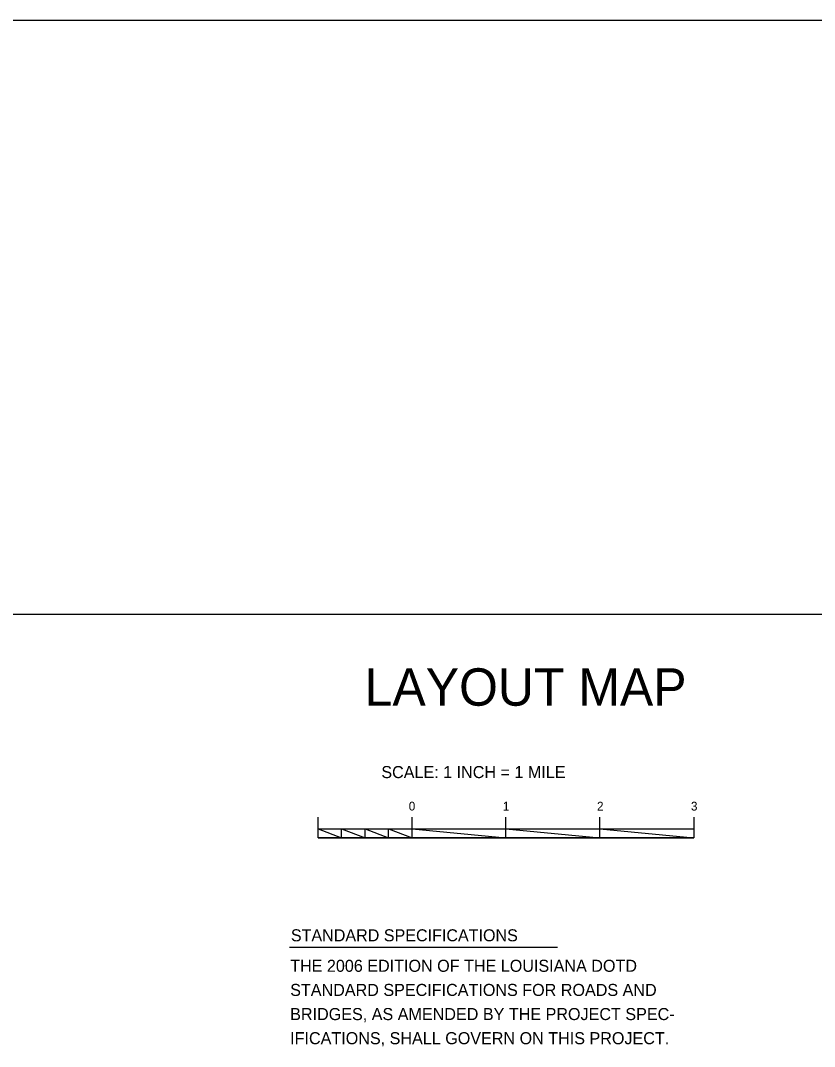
# Model space of a CAD drawing. Extents: x 0.19 to 2.82, y 0.04 to 1.79.
# Drawn here: x 1.074 to 1.779, y 0.111 to 1.021 of the extents above; entities that cross this region are included whole.
import ezdxf

# ---------------------------------------------------------------- set-up
doc = ezdxf.new("R2010")
doc.units = 0
doc.layers.add('Layout Map Info', color=7, linetype='Continuous')
doc.layers.add('Standard Info', color=7, linetype='Continuous')

msp = doc.modelspace()

# ---------------------------------------------------------------- linework, layer by layer
at = {"layer": 'Layout Map Info'}
msp.add_lwpolyline([(0.90383, 0.49428), (2.1045, 0.49428), (2.1045, 1.02062), (0.90383, 1.02062)], close=True, dxfattribs=at)
at = {"layer": 'Standard Info'}
for p, q in [((1.33813, 0.29606), (1.33813, 0.31439)), ((1.42146, 0.29606), (1.42146, 0.31439)), ((1.5048, 0.29606), (1.5048, 0.31439)), ((1.58813, 0.29606), (1.58813, 0.31439)), ((1.67146, 0.31439), (1.67146, 0.29606)), ((1.33813, 0.30389), (1.67146, 0.30389)), ((1.33813, 0.29606), (1.67146, 0.29606)), ((1.31266, 0.19914), (1.55045, 0.19914))]:
    msp.add_line(p, q, dxfattribs=at)
for points in [[(1.33813, 0.29606), (1.33813, 0.30389), (1.35888, 0.29606)], [(1.35896, 0.29606), (1.35896, 0.30389), (1.3798, 0.29606)], [(1.37996, 0.29606), (1.37996, 0.30389), (1.40071, 0.29606)], [(1.40063, 0.29606), (1.40063, 0.30389), (1.42146, 0.29606)], [(1.42146, 0.29606), (1.42146, 0.30389), (1.5048, 0.29606)], [(1.5048, 0.29606), (1.5048, 0.30389), (1.58813, 0.29606)], [(1.58813, 0.29606), (1.58813, 0.30389), (1.67146, 0.29606)]]:
    msp.add_lwpolyline(points, close=True, dxfattribs=at)

# ---------------------------------------------------------------- texts
for s, height, p in [('LAYOUT MAP', 0.03313, (1.37947, 0.41312)), ('SCALE: 1 INCH = 1 MILE', 0.0107, (1.39425, 0.34891)), ('0', 0.0078, (1.41856, 0.32015)), ('1', 0.0078, (1.50206, 0.32015)), ('2', 0.0078, (1.5856, 0.32015)), ('3', 0.0078, (1.6689, 0.32015)), ('STANDARD SPECIFICATIONS', 0.01067, (1.314, 0.20421)), ('THE 2006 EDITION OF THE LOUISIANA DOTD', 0.0107, (1.31337, 0.17717)), ('STANDARD SPECIFICATIONS FOR ROADS AND ', 0.0107, (1.31337, 0.15577)), ('BRIDGES, AS AMENDED BY THE PROJECT SPEC-', 0.0107, (1.31337, 0.13437)), ('IFICATIONS, SHALL GOVERN ON THIS PROJECT.', 0.0107, (1.31337, 0.11297))]:
    msp.add_text(s, height=height, dxfattribs=at).set_placement(p)

doc.saveas('drawing.dxf')
